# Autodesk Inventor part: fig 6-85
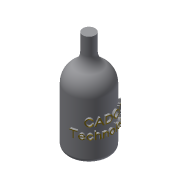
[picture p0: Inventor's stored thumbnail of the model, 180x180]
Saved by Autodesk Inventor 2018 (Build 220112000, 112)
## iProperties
Shininess: 64.0
Length Units: 11269
Angle Units: 11279
Time Units: 11290
Mass Units: 11283
Length Display Precision: 3
Angle Display Precision: 2
Compacted: True
Part Number: fig 6-85
Document SubType Name: Modeling
Created: 2002-12
Designer: deepak
Density: 1 g/cm^3
Material: Generic
Appearance: Default
Density: 0.0
Volumn: 0.0
Area: 0.0
PropertySet Name: Model Information
Control State: 0
Master: False
Checked Out: False
Author: deepak
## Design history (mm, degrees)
node "Sketch1"
sketch "Sketch2"
  geometry: L1 (-7.653, 24.992)-(-7.653, 16.776); L2 (-14.653, 3.659)-(-14.653, -3.57); L3 (-14.653, -3.57)-(-14.653, -23.329); L4 (-14.653, -23.329)-(-4.653, -23.329); L5 (-4.653, -23.329)-(-4.653, 24.992); L6 (-4.653, 24.992)-(-7.653, 24.992); A1 r 6.757 centre (-14.41, 16.776) between (-10.649, 11.163) and (-7.653, 16.776); A2 r 9.033 centre (-5.62, 3.659) between (-10.649, 11.163) and (-14.653, 3.659)
  constraints: 12 end point, 4 point on circle, 3 tangent, 2 centre point, 2 parallel, 2 perpendicular, 1 collinear, 1 vertical
  dimensions: "d0" = 3 distance of L5.end L1.start; "d1" = 10 distance of L3.end L4.end
revolve "Revolution1" sketch "Sketch2" stored, may be unused: angle "d2" = 90 deg
fillet "Fillet1" dims "d3" = 2
workplane "Work Plane1"
workplane "Work Plane2"
sketch "Sketch3"
  geometry: L1 (-24.815, -3.793)-(24.913, -3.793); L2 (24.913, -3.793)-(24.913, -8.382); L3 (24.913, -8.382)-(-24.815, -8.382); L4 (-24.815, -8.382)-(-24.815, -3.793)
  constraints: 2 other
emboss "Emboss1" sketch "Sketch3" dims "d5" = 1, "d6" = 0
body "Solid1"
other parameters: "d4" = 3.5
